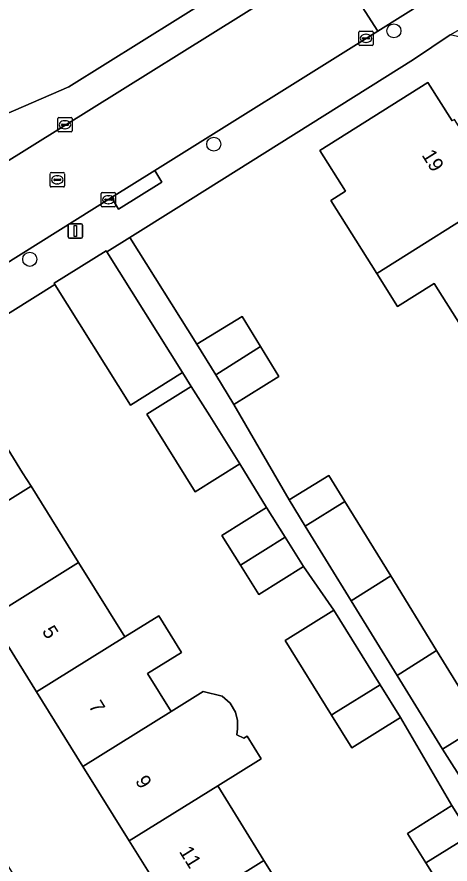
# Model space of a CAD drawing. Extents: x 159352 to 160617, y 385888 to 387323.
# Drawn here: x 159703.5 to 159733.6, y 386145.6 to 386204.5 of the extents above; entities that cross this region are included whole.
import ezdxf

# ---------------------------------------------------------------- set-up
doc = ezdxf.new("R2010")
doc.units = 0
for name, color, linetype in [('IMGEO_Boom', 7, 'Continuous'), ('IMGEO_Erf', 7, 'Continuous'), ('IMGEO_Kolk', 7, 'Continuous'), ('IMGEO_Lichtmast', 7, 'Continuous'), ('IMGEO_Muur', 7, 'Continuous'), ('IMGEO_Pand', 7, 'Continuous'), ('IMGEO_Pand_nummerreeks', 7, 'Continuous'), ('IMGEO_Rijbaan_lokaal_open', 7, 'Continuous'), ('IMGEO_Rioolput', 7, 'Continuous'), ('IMGEO_Voetpad_open', 7, 'Continuous')]:
    doc.layers.add(name, color=color, linetype=linetype)

msp = doc.modelspace()

# ---------------------------------------------------------------- linework, layer by layer
at = {"layer": 'IMGEO_Boom'}
for centre in [(159729.71, 386203.582), (159717.188, 386195.701), (159704.397, 386187.696)]:
    msp.add_circle(centre, 0.489, dxfattribs=at)
at = {"layer": 'IMGEO_Erf'}
for points in [[(159659.692, 386207.676), (159651.93, 386204.377), (159652.706, 386202.574), (159652.195, 386201.7), (159650.461, 386200.954), (159649.448, 386203.309), (159647.553, 386202.475), (159648.558, 386200.141), (159645.044, 386198.629), (159642.092, 386197.359), (159641.088, 386199.692), (159614.885, 386188.675), (159616.371, 386185.229), (159610.171, 386182.682), (159608.419, 386181.908), (159612.907, 386171.428), (159617.444, 386160.891), (159669.117, 386183.212), (159707.116, 386199.677), (159719.747, 386207.6)], [(159765.891, 386141.835), (159772.114, 386145.744), (159736.577, 386202.635), (159733.614, 386203.294), (159731.071, 386201.577), (159714.574, 386191.233), (159711.363, 386189.221), (159716.018, 386181.79), (159719.157, 386183.716), (159720.439, 386181.626), (159721.721, 386179.537), (159718.582, 386177.611), (159722.427, 386170.969), (159725.189, 386172.667), (159726.296, 386170.867), (159729.487, 386165.678), (159732.679, 386160.486), (159735.84, 386155.345), (159733.077, 386153.646), (159739.919, 386142.917)], [(159734.325, 386183.112), (159732.499, 386186.019), (159729.948, 386184.414), (159728.511, 386186.701), (159725.32, 386191.78), (159726.351, 386192.428), (159724.564, 386195.272), (159732.069, 386199.987), (159733.747, 386197.316)], [(159733.216, 386143.666), (159731.929, 386145.722), (159730.642, 386147.777), (159733.744, 386149.721), (159730.165, 386155.842), (159726.781, 386153.737), (159725.367, 386156.01), (159722.148, 386161.186), (159725.532, 386163.291), (159723.428, 386166.327), (159720.325, 386164.383), (159719.037, 386166.44), (159717.751, 386168.494), (159720.853, 386170.438), (159718.998, 386173.467), (159715.904, 386171.529), (159712.527, 386176.922), (159715.626, 386178.852), (159715.021, 386179.818), (159711.398, 386177.548), (159706.136, 386185.947), (159685.685, 386173.135), (159722.272, 386114.357)], [(159701.262, 386177.103), (159703.904, 386172.858), (159704.49, 386171.917), (159707.785, 386166.62), (159711.009, 386161.441), (159713.358, 386162.901), (159714.936, 386160.364), (159712.587, 386158.904), (159714.231, 386156.262), (159716.439, 386157.635), (159717.774, 386157.324), (159718.327, 386156.824), (159718.704, 386156.203), (159718.837, 386155.626), (159718.826, 386155.061), (159718.78, 386154.627), (159719.276, 386154.403), (159719.504, 386154.545), (159720.485, 386152.968), (159717.46, 386151.087), (159720.677, 386145.904), (159722.108, 386143.604)], [(159714.541, 386142.083), (159711.318, 386147.263), (159708.095, 386152.441), (159704.872, 386157.62), (159701.649, 386162.8)]]:
    msp.add_lwpolyline(points, dxfattribs=at)
at = {"layer": 'IMGEO_Kolk'}
for p, q in [((159727.268, 386202.634), (159727.268, 386203.486)), ((159727.343, 386203.56), (159728.195, 386203.56)), ((159727.756, 386203.34), (159727.781, 386203.34)), ((159728.269, 386203.486), (159728.269, 386202.634)), ((159727.527, 386203.054), (159727.527, 386203.066)), ((159727.965, 386203.017), (159727.567, 386203.017)), ((159727.57, 386203.103), (159727.968, 386203.103)), ((159727.779, 386202.78), (159727.754, 386202.78)), ((159728.011, 386203.066), (159728.011, 386203.054)), ((159728.195, 386202.56), (159727.343, 386202.56)), ((159706.344, 386196.624), (159706.344, 386197.476)), ((159706.419, 386197.55), (159707.271, 386197.55)), ((159707.345, 386197.476), (159707.345, 386196.624)), ((159706.603, 386197.044), (159706.603, 386197.056)), ((159707.041, 386197.007), (159706.643, 386197.007)), ((159706.646, 386197.093), (159707.044, 386197.093)), ((159706.832, 386197.33), (159706.857, 386197.33)), ((159707.087, 386197.056), (159707.087, 386197.044)), ((159707.271, 386196.55), (159706.419, 386196.55)), ((159706.855, 386196.77), (159706.83, 386196.77)), ((159709.362, 386191.414), (159709.362, 386192.266)), ((159709.437, 386192.34), (159710.289, 386192.34)), ((159709.85, 386192.12), (159709.875, 386192.12)), ((159710.363, 386192.266), (159710.363, 386191.414)), ((159709.621, 386191.834), (159709.621, 386191.846)), ((159710.059, 386191.797), (159709.661, 386191.797)), ((159709.664, 386191.883), (159710.062, 386191.883)), ((159709.873, 386191.56), (159709.848, 386191.56)), ((159710.105, 386191.846), (159710.105, 386191.834)), ((159710.289, 386191.34), (159709.437, 386191.34))]:
    msp.add_line(p, q, dxfattribs=at)
for points in [[(159727.268, 386202.634), (159727.268, 386203.486)], [(159727.343, 386203.56), (159728.195, 386203.56)], [(159728.269, 386203.486), (159728.269, 386202.634)], [(159728.195, 386202.56), (159727.343, 386202.56)], [(159706.344, 386196.624), (159706.344, 386197.476)], [(159706.419, 386197.55), (159707.271, 386197.55)], [(159707.345, 386197.476), (159707.345, 386196.624)], [(159707.271, 386196.55), (159706.419, 386196.55)], [(159709.362, 386191.414), (159709.362, 386192.266)], [(159709.437, 386192.34), (159710.289, 386192.34)], [(159710.363, 386192.266), (159710.363, 386191.414)], [(159710.289, 386191.34), (159709.437, 386191.34)]]:
    msp.add_lwpolyline(points, dxfattribs=at)
for centre, radius, start, end in [((159727.345, 386203.484), 0.0765, 91.55205, 178.44795), ((159727.345, 386203.484), 0.0765, 91.55205, 178.44795), ((159728.193, 386203.484), 0.0765, 1.55205, 88.44795), ((159728.193, 386203.484), 0.0765, 1.55205, 88.44795), ((159727.567, 386203.063), 0.0403, 85.87752, 175.75265), ((159727.564, 386203.053), 0.0366, 178.93798, 274.71019), ((159727.968, 386203.06), 0.043, 264.86636, 352.45326), ((159727.972, 386203.065), 0.0386, 1.73085, 96.63898), ((159727.345, 386202.636), 0.0765, 181.55205, 268.44795), ((159727.345, 386202.636), 0.0765, 181.55205, 268.44795), ((159728.193, 386202.636), 0.0765, 271.55205, 358.44795), ((159728.193, 386202.636), 0.0765, 271.55205, 358.44795), ((159706.421, 386197.474), 0.0765, 91.55205, 178.44795), ((159706.421, 386197.474), 0.0765, 91.55205, 178.44795), ((159707.269, 386197.474), 0.0765, 1.55205, 88.44795), ((159707.269, 386197.474), 0.0765, 1.55205, 88.44795), ((159706.643, 386197.053), 0.0403, 85.87752, 175.75265), ((159706.64, 386197.043), 0.0366, 178.93798, 274.71019), ((159707.044, 386197.05), 0.043, 264.86636, 352.45326), ((159707.048, 386197.055), 0.0386, 1.73085, 96.63898), ((159706.421, 386196.626), 0.0765, 181.55205, 268.44795), ((159706.421, 386196.626), 0.0765, 181.55205, 268.44795), ((159707.269, 386196.626), 0.0765, 271.55205, 358.44795), ((159707.269, 386196.626), 0.0765, 271.55205, 358.44795), ((159709.439, 386192.264), 0.0765, 91.55205, 178.44795), ((159709.439, 386192.264), 0.0765, 91.55205, 178.44795), ((159710.287, 386192.264), 0.0765, 1.55205, 88.44795), ((159710.287, 386192.264), 0.0765, 1.55205, 88.44795), ((159709.661, 386191.843), 0.0403, 85.87752, 175.75265), ((159709.658, 386191.833), 0.0366, 178.93798, 274.71019), ((159710.062, 386191.84), 0.043, 264.86636, 352.45326), ((159710.066, 386191.845), 0.0386, 1.73085, 96.63898), ((159709.439, 386191.416), 0.0765, 181.55205, 268.44795), ((159709.439, 386191.416), 0.0765, 181.55205, 268.44795), ((159710.287, 386191.416), 0.0765, 271.55205, 358.44795), ((159710.287, 386191.416), 0.0765, 271.55205, 358.44795)]:
    msp.add_arc(centre, radius, start, end, dxfattribs=at)
for centre, major_axis, ratio, start_param, end_param in [((159727.755, 386203.06), (-0.387, 0.002), 0.722429, 4.712389, 7.853982), ((159727.78, 386203.06), (-0.39, 0.002), 0.717154, 1.570796, 4.712389), ((159706.831, 386197.05), (-0.387, 0.002), 0.722429, 4.712389, 7.853982), ((159706.856, 386197.05), (-0.39, 0.002), 0.717154, 1.570796, 4.712389), ((159709.849, 386191.84), (-0.387, 0.002), 0.722429, 4.712389, 7.853982), ((159709.874, 386191.84), (-0.39, 0.002), 0.717154, 1.570796, 4.712389)]:
    msp.add_ellipse(centre, major_axis=major_axis, ratio=ratio, start_param=start_param, end_param=end_param, dxfattribs=at)
at = {"layer": 'IMGEO_Lichtmast'}
for p, q in [((159707.07, 386189.263), (159707.07, 386190.063)), ((159707.07, 386190.063), (159707.07, 386189.263)), ((159707.17, 386190.163), (159707.96, 386190.163)), ((159707.96, 386190.163), (159707.17, 386190.163)), ((159708.06, 386190.063), (159708.06, 386189.263)), ((159708.06, 386189.263), (159708.06, 386190.063)), ((159707.96, 386189.163), (159707.17, 386189.163)), ((159707.17, 386189.163), (159707.96, 386189.163))]:
    msp.add_line(p, q, dxfattribs=at)
msp.add_lwpolyline([(159707.49, 386190.038), (159707.64, 386190.038), (159707.64, 386189.288), (159707.49, 386189.288), (159707.49, 386190.038)], dxfattribs=at)
for centre, start, end in [((159707.17, 386190.063), 90, 180), ((159707.17, 386190.063), 90, 180), ((159707.96, 386190.063), 0, 90), ((159707.96, 386190.063), 360, 90), ((159707.17, 386189.263), 180, 270), ((159707.17, 386189.263), 180, 270), ((159707.96, 386189.263), 270, 0), ((159707.96, 386189.263), 270, 0)]:
    msp.add_arc(centre, 0.1, start, end, dxfattribs=at)
at = {"layer": 'IMGEO_Muur'}
msp.add_lwpolyline([(159714.574, 386191.233), (159731.071, 386201.577)], dxfattribs=at)
at = {"layer": 'IMGEO_Pand'}
for points in [[(159737.217, 386192.175), (159733.919, 386197.424), (159733.747, 386197.316), (159732.069, 386199.987), (159724.564, 386195.272), (159726.351, 386192.428), (159725.32, 386191.78), (159728.511, 386186.701)], [(159728.511, 386186.701), (159729.948, 386184.414), (159732.499, 386186.019), (159734.325, 386183.112), (159740.48, 386186.981), (159737.217, 386192.175)], [(159709.758, 386188.216), (159709.709, 386188.295), (159706.086, 386186.026), (159706.136, 386185.947), (159711.398, 386177.548), (159715.021, 386179.818)], [(159720.439, 386181.626), (159719.157, 386183.716), (159716.018, 386181.79), (159717.321, 386179.665)], [(159718.582, 386177.611), (159721.721, 386179.537), (159720.439, 386181.626), (159717.321, 386179.665)], [(159715.626, 386178.852), (159712.527, 386176.922), (159715.904, 386171.529), (159718.998, 386173.467), (159716.909, 386176.803)], [(159704.49, 386171.917), (159703.904, 386172.858), (159701.262, 386177.103), (159695.125, 386173.284), (159698.354, 386168.096)], [(159723.55, 386169.141), (159726.296, 386170.867), (159725.189, 386172.667), (159722.427, 386170.969)], [(159707.785, 386166.62), (159704.49, 386171.917), (159698.354, 386168.096), (159701.649, 386162.8)], [(159720.853, 386170.438), (159717.751, 386168.494), (159719.037, 386166.44), (159722.145, 386168.375)], [(159726.296, 386170.867), (159723.55, 386169.141), (159726.741, 386163.952), (159729.487, 386165.678)], [(159720.325, 386164.383), (159723.428, 386166.327), (159722.145, 386168.375), (159719.037, 386166.44)], [(159701.649, 386162.8), (159704.872, 386157.62), (159711.009, 386161.441), (159707.785, 386166.62)], [(159729.487, 386165.678), (159726.741, 386163.952), (159729.933, 386158.76), (159732.679, 386160.486)], [(159725.532, 386163.291), (159722.148, 386161.186), (159725.367, 386156.01), (159725.528, 386156.11), (159728.75, 386158.116)], [(159704.872, 386157.62), (159708.095, 386152.441), (159714.231, 386156.262), (159712.587, 386158.904), (159714.936, 386160.364), (159713.358, 386162.901), (159711.009, 386161.441)], [(159732.679, 386160.486), (159729.933, 386158.76), (159733.077, 386153.646), (159735.84, 386155.345)], [(159728.75, 386158.116), (159725.528, 386156.11), (159725.367, 386156.01), (159726.781, 386153.737), (159730.165, 386155.842)], [(159720.485, 386152.968), (159719.504, 386154.545), (159719.276, 386154.403), (159718.78, 386154.627), (159718.826, 386155.061), (159718.837, 386155.626), (159718.704, 386156.203), (159718.327, 386156.824), (159717.774, 386157.324), (159716.439, 386157.635), (159714.231, 386156.262), (159708.095, 386152.441), (159711.318, 386147.263), (159717.46, 386151.087)], [(159720.677, 386145.904), (159717.46, 386151.087), (159711.318, 386147.263), (159714.541, 386142.083)], [(159733.744, 386149.721), (159730.642, 386147.777), (159731.929, 386145.722), (159735.037, 386147.657)], [(159733.216, 386143.666), (159736.319, 386145.61), (159735.037, 386147.657), (159731.929, 386145.722)], [(159714.541, 386142.083), (159717.764, 386136.904), (159723.9, 386140.724), (159726.218, 386142.17), (159724.427, 386145.049), (159722.108, 386143.604), (159720.677, 386145.904)]]:
    msp.add_lwpolyline(points, close=True, dxfattribs=at)
at = {"layer": 'IMGEO_Rijbaan_lokaal_open'}
msp.add_lwpolyline([(159727.392, 386209.887), (159725.377, 386208.588), (159728.58, 386203.569), (159731.871, 386205.614)], dxfattribs=at)
msp.add_lwpolyline([(159710.076, 386191.982), (159713.085, 386193.866), (159728.58, 386203.569), (159725.377, 386208.588), (159702.417, 386194.251), (159699.204, 386192.245), (159698.284, 386191.67), (159686.801, 386184.624), (159690.037, 386179.433)], close=True, dxfattribs=at)
at = {"layer": 'IMGEO_Rioolput'}
for p, q in [((159705.813, 386192.798), (159705.813, 386193.65)), ((159705.888, 386193.724), (159706.74, 386193.724)), ((159706.301, 386193.504), (159706.326, 386193.504)), ((159706.814, 386193.65), (159706.814, 386192.798)), ((159706.74, 386192.724), (159705.888, 386192.724)), ((159706.072, 386193.218), (159706.072, 386193.23)), ((159706.51, 386193.181), (159706.112, 386193.181)), ((159706.115, 386193.267), (159706.513, 386193.267)), ((159706.324, 386192.944), (159706.299, 386192.944)), ((159706.556, 386193.23), (159706.556, 386193.218))]:
    msp.add_line(p, q, dxfattribs=at)
for points in [[(159705.813, 386192.798), (159705.813, 386193.65)], [(159705.888, 386193.724), (159706.74, 386193.724)], [(159706.814, 386193.65), (159706.814, 386192.798)], [(159706.74, 386192.724), (159705.888, 386192.724)]]:
    msp.add_lwpolyline(points, dxfattribs=at)
for centre, radius, start, end in [((159705.89, 386193.648), 0.0765, 91.55205, 178.44795), ((159705.89, 386193.648), 0.0765, 91.55205, 178.44795), ((159706.738, 386193.648), 0.0765, 1.55205, 88.44795), ((159706.738, 386193.648), 0.0765, 1.55205, 88.44795), ((159705.89, 386192.8), 0.0765, 181.55205, 268.44795), ((159705.89, 386192.8), 0.0765, 181.55205, 268.44795), ((159706.112, 386193.227), 0.0403, 85.87752, 175.75265), ((159706.109, 386193.217), 0.0366, 178.93798, 274.71019), ((159706.513, 386193.224), 0.043, 264.86636, 352.45326), ((159706.517, 386193.229), 0.0386, 1.73085, 96.63898), ((159706.738, 386192.8), 0.0765, 271.55205, 358.44795), ((159706.738, 386192.8), 0.0765, 271.55205, 358.44795)]:
    msp.add_arc(centre, radius, start, end, dxfattribs=at)
for centre, major_axis, ratio, start_param, end_param in [((159706.3, 386193.224), (-0.387, 0.002), 0.722429, 4.712389, 7.853982), ((159706.325, 386193.224), (-0.39, 0.002), 0.717154, 1.570796, 4.712389)]:
    msp.add_ellipse(centre, major_axis=major_axis, ratio=ratio, start_param=start_param, end_param=end_param, dxfattribs=at)
at = {"layer": 'IMGEO_Voetpad_open'}
for points in [[(159662.86, 386172.145), (159666.048, 386174.133), (159665.998, 386174.271), (159663.38, 386178.426), (159669.578, 386181.115), (159670.692, 386181.586), (159671.129, 386180.658), (159672.791, 386181.378), (159672.385, 386182.329), (159678.601, 386185.01), (159679.843, 386182.982), (159679.947, 386182.816), (159683.126, 386184.832), (159683.351, 386184.43), (159692.137, 386189.957), (159691.793, 386190.467), (159685.357, 386186.443), (159684.781, 386187.668), (159691.207, 386190.458), (159698.352, 386193.525), (159698.969, 386192.653), (159702.158, 386194.63), (159702.417, 386194.251), (159725.377, 386208.588)], [(159719.747, 386207.6), (159707.116, 386199.677), (159669.117, 386183.212), (159617.444, 386160.891), (159618.283, 386158.932), (159620.325, 386159.832), (159620.711, 386159), (159622.308, 386159.737), (159621.986, 386160.533), (159623.907, 386161.387), (159638.878, 386167.868), (159641.058, 386168.783), (159645.566, 386161.501), (159645.652, 386161.379), (159648.843, 386163.369), (159648.755, 386163.513), (159644.576, 386170.32)], [(159731.071, 386201.577), (159733.614, 386203.294), (159737.967, 386205.8)], [(159731.871, 386205.614), (159728.58, 386203.569), (159713.085, 386193.866), (159713.589, 386193.057), (159710.577, 386191.178), (159710.076, 386191.982), (159690.037, 386179.433), (159685.663, 386176.667)], [(159682.747, 386171.384), (159685.685, 386173.135), (159706.136, 386185.947), (159706.086, 386186.026), (159709.709, 386188.295), (159709.758, 386188.216), (159711.363, 386189.221), (159714.574, 386191.233), (159731.071, 386201.577)], [(159739.919, 386142.917), (159733.077, 386153.646), (159729.933, 386158.76), (159726.741, 386163.952), (159723.55, 386169.141), (159722.427, 386170.969), (159718.582, 386177.611), (159717.321, 386179.665), (159716.018, 386181.79), (159711.363, 386189.221), (159709.758, 386188.216), (159715.021, 386179.818), (159715.626, 386178.852), (159716.909, 386176.803), (159718.998, 386173.467), (159720.853, 386170.438), (159722.145, 386168.375), (159723.428, 386166.327), (159725.532, 386163.291), (159728.75, 386158.116), (159730.165, 386155.842), (159733.744, 386149.721), (159735.037, 386147.657), (159736.319, 386145.61)]]:
    msp.add_lwpolyline(points, dxfattribs=at)
msp.add_lwpolyline([(159710.076, 386191.982), (159710.577, 386191.178), (159713.589, 386193.057), (159713.085, 386193.866)], close=True, dxfattribs=at)

# ---------------------------------------------------------------- texts
at = {"layer": 'IMGEO_Pand_nummerreeks'}
for s, rotation, p in [('19', 302.13969, (159731.609, 386194.944)), ('5', 301.89314, (159705.216, 386161.837)), ('7', 301.89314, (159708.455, 386156.632)), ('9', 301.89062, (159711.694, 386151.427)), ('11', 301.89314, (159714.75, 386146.516))]:
    msp.add_text(s, height=1, rotation=rotation, dxfattribs=at).set_placement(p)

doc.saveas('drawing.dxf')
